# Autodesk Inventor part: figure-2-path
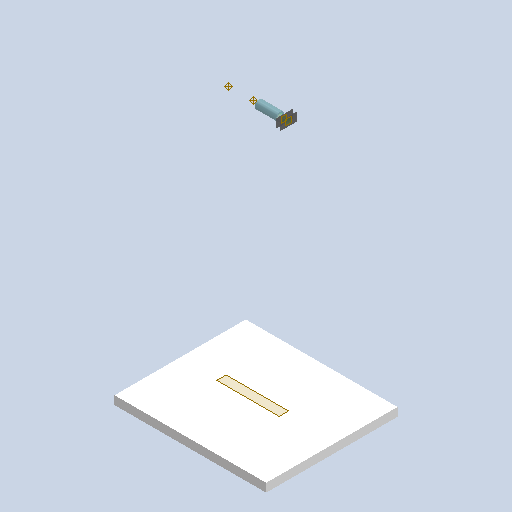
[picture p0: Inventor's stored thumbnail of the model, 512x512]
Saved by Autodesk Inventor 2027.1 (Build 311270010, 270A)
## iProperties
Created: 2026-09
Part Number: figure-2-path
Material: Generic
Document SubType Name: Modeling
Designer: dunge
Density: 1 g/cm^3
Appearance: Default
Author: dunge
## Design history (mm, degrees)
sketch "GRIN-sketch"
  geometry: L1 (0, 0)-(-73.025, 0); L2 (-73.025, -3.175)-(-73.025, 3.175); L3 (-73.025, 3.175)-(-92.075, -7.62); L4 (-92.075, -7.62)-(-92.075, 7.62); L5 (-92.075, 7.62)-(-73.025, -3.175); L6 (-73.025, 0)-(-92.075, 0); L7 (-92.075, 7.62)-(-90.805, 7.62); L8 (-90.805, 7.62)-(-90.805, 12.7); L9 (-90.805, 12.7)-(-154.305, 12.7); L10 (-154.305, 12.7)-(-154.305, 7.62); L11 (-154.305, 7.62)-(-153.035, 7.62); L12 (-153.035, 7.62)-(-153.035, 0); L13 (-153.035, 0)-(-92.075, 0); 3 further points
  constraints: 27 end point, 5 perpendicular, 5 point on line, 2 horizontal, 2 midpoint, 1 parallel, 1 vertical
  dimensions: "d0" = 73.025 distance of L1.end L1.start; "d1" = 6.35 distance of L2.start L2.end; "d3" = 1.27 distance of L4.end L7.end; "d4" = 1.27 distance of L10.end L11.end; "d5" = 12.7 distance between parallel lines of L13 L9; "d6" = 63.5 distance of L8.end L9.end; "d7" = 15.24 distance of L3.end L4.end; "d8" = 19.05 distance of L1.end L6.end
workpoint "Work Point1"
workpoint "Work Point2"
revolve "Revolution1" stored, may be unused: angle "d2" = 360 deg
workpoint "Work Point3"
revolve "Revolution2" stored, may be unused: angle "d9" = 360 deg
workplane "Work Plane1"
sketch "Sketch2"
  geometry: L1 (135.016, 204.838)-(-317.177, 204.838); L2 (-317.177, 204.838)-(-317.177, -186.688); L3 (-317.177, -186.688)-(135.016, -186.688); L4 (135.016, -186.688)-(135.016, 204.838); 1 further point
  constraints: 8 end point, 2 parallel, 1 horizontal, 1 perpendicular
extrude "Extrusion1" new body sketch "Sketch2" distance "d11" = 25.4; taper "d12" = 0 deg
sketch "Sketch3"
  geometry: L1 (-153.035, -7.62)-(-153.035, 7.62) reference; L2 (-153.035, 7.62)-(-165.735, 0); L3 (-165.735, 0)-(-153.035, 0); 1 further point
  constraints: 4 end point, 1 horizontal, 1 midpoint
  dimensions: "d13" = 12.7 distance of L2.end L3.end
revolve "Revolution3" sketch "Sketch3" stored, may be unused: angle "d14" = 360 deg
sketch "red-side-beam-sketch"
  geometry: L1 (-153.035, -7.62)-(-153.035, 7.62) reference; L2 (-153.035, 7.62)-(-165.735, -2.54); L3 (-165.735, -2.54)-(-150.285, -7.62); L4 (-165.735, -2.54)-(-151.66, 0); L5 (-151.66, 0)-(-153.035, 7.62); L6 (-151.66, 0)-(-150.285, -7.62); L7 (-165.735, 0)-(-153.035, 7.62) reference; L8 (-165.735, 0)-(-153.035, -7.62) reference; 1 further point
  constraints: 10 end point, 2 perpendicular, 1 collinear, 1 horizontal alignment, 1 vertical alignment
  dimensions: "d15" = 2.54 distance of L7.start L2.end
revolve "Revolution4" sketch "red-side-beam-sketch" stored, may be unused: angle "d16" = 360 deg
workplane "Work Plane2"
sketch "Sketch5"
  geometry: L1 (25.4, -12.7)-(-25.4, -12.7); L2 (-25.4, -12.7)-(-25.4, 12.7); L3 (-25.4, 12.7)-(25.4, 12.7); L4 (25.4, 12.7)-(25.4, -12.7); L5 (25.4, -12.7)-(-25.4, 12.7); L6 (-25.4, -12.7)-(25.4, 12.7); 1 further point
  constraints: 12 end point, 2 midpoint, 2 parallel, 1 horizontal, 1 perpendicular
  dimensions: "d23" = 25.4 distance of L1.end L2.end; "d24" = 50.8 distance of L2.end L3.end
extrude "Extrusion2" new body sketch "Sketch5" distance "d18" = 1.27; taper "d19" = 0 deg
workplane "Work Plane3"
sketch "Sketch6"
  geometry: L1 (-25.4, 12.7)-(25.4, 12.7) reference; L2 (25.4, 12.7)-(25.4, -12.7) reference; L3 (25.4, -12.7)-(-25.4, -12.7) reference; L4 (-25.4, -12.7)-(-25.4, 12.7) reference; 2 further points
extrude "Extrusion3" new body sketch "Sketch6" distance "d21" = 1.27; taper "d22" = 0 deg
sketch "Sketch7"
  geometry: L1 (-165.735, 0)-(-153.035, 7.62) reference; L2 (-153.035, 7.62)-(-178.435, 0); L3 (-178.435, -25.4)-(-178.435, 25.4) reference; L4 (-153.035, -7.62)-(-153.035, 7.62) reference; L5 (-153.035, 0)-(-153.035, 7.62); L6 (-178.435, 0)-(-153.035, 0); L7 (-150.285, -7.62)-(-153.035, 7.62) reference; L8 (-153.035, 7.62)-(-153.035, 0); 2 further points
  constraints: 8 end point, 2 collinear, 2 midpoint, 1 horizontal, 1 point on line
revolve "Revolution5" sketch "Sketch7" stored, may be unused: angle "d25" = 360 deg
sketch "Sketch8"
  geometry: L1 (-165.735, 0)-(-153.035, 7.62) reference; L2 (-165.735, 0)-(-153.035, -7.62) reference; L3 (-153.035, -7.62)-(-153.035, 7.62) reference; 1 further point
extrude "Extrusion4" cut sketch "Sketch8" extent not by distance; stored distance "d26" = 0; taper "d27" = 0 deg
node "red-beam"
node "Finishes"
node "GRIN"
node "white-background"
node "green-beam"
node "red-side-beam"
node "black-plante-near"
node "black-plane-far"
node "extra-red-beam"
node "Finish1" dims "Finish1_Area" = 64.83201
node "Finish2" dims "Finish2_Area" = 620.20995
node "Finish3" dims "Finish3_Area" = 17704.58546
node "Finish4" dims "Finish4_Area" = 53.69651
node "Finish5" dims "Finish5_Area" = 119.67071
node "Finish6" dims "Finish6_Area" = 554.8376
node "Finish7" dims "Finish7_Area" = 18.24147
node "Finish8" dims "Finish8_Area" = 18.24147
node "Finish9" dims "Finish9_Area" = 61.27217
other parameters: "d10" = -762, "d17" = -12.7, "d20" = -12.7
